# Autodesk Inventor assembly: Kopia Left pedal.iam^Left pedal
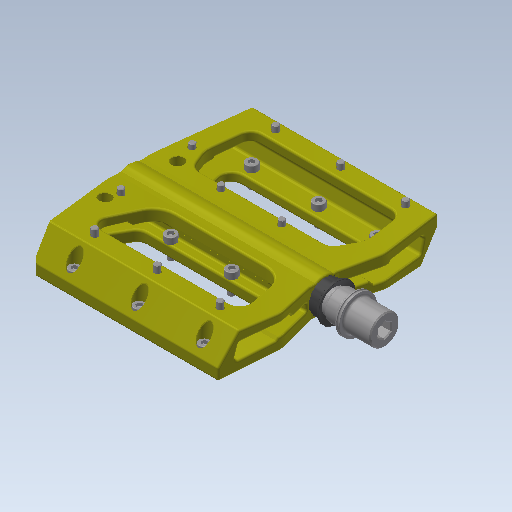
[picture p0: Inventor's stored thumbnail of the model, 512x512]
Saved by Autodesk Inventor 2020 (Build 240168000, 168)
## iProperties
Created: 2017-10
Part Number: Kopia Left pedal.iam^Left pedal
Material: Ogólny
Document SubType Name: Assembly
Designer: Tomasz
Sending System: SolidWorks 2017
Last Author: Tomasz
Last Saved: 2017-11-20
Author: Tomasz
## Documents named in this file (9)
- C:\Users\bruno\Documents\1-Cours-2020-21\1STI2D-2020-21\IT\6. Antivol\Inventor-Antivol\INVENTOR 2018_Steel Hardtail B+\Kopia Left pedal.iam^Left pedal.iam
- C:\Users\bruno\Documents\1-Cours-2020-21\1STI2D-2020-21\IT\6. Antivol\Inventor-Antivol\INVENTOR 2018_Steel Hardtail B+\Kopia full left platform body.ipt^Kopia Left pedal.iam_Left pedal.ipt
- C:\Users\bruno\Documents\1-Cours-2020-21\1STI2D-2020-21\IT\6. Antivol\Inventor-Antivol\INVENTOR 2018_Steel Hardtail B+\Kopia Left pedal axle.ipt^Kopia Left pedal.iam_Left pedal.ipt
- C:\Users\bruno\Documents\1-Cours-2020-21\1STI2D-2020-21\IT\6. Antivol\Inventor-Antivol\INVENTOR 2018_Steel Hardtail B+\Kopia Axle nut.ipt^Kopia Left pedal.iam_Left pedal.ipt
- C:\Users\bruno\Documents\1-Cours-2020-21\1STI2D-2020-21\IT\6. Antivol\Inventor-Antivol\INVENTOR 2018_Steel Hardtail B+\Kopia bushing.ipt^Kopia Left pedal.iam_Left pedal.ipt
- C:\Users\bruno\Documents\1-Cours-2020-21\1STI2D-2020-21\IT\6. Antivol\Inventor-Antivol\INVENTOR 2018_Steel Hardtail B+\Kopia Hex bolt axle cap.ipt^Kopia Left pedal.iam_Left pedal.ipt
- C:\Users\bruno\Documents\1-Cours-2020-21\1STI2D-2020-21\IT\6. Antivol\Inventor-Antivol\INVENTOR 2018_Steel Hardtail B+\Kopia seal.ipt^Kopia Left pedal.iam_Left pedal.ipt
- C:\Users\bruno\Documents\1-Cours-2020-21\1STI2D-2020-21\IT\6. Antivol\Inventor-Antivol\INVENTOR 2018_Steel Hardtail B+\Kopia 686-2RS.iam^Kopia Left pedal.iam_Left pedal.iam
- C:\Users\bruno\Documents\1-Cours-2020-21\1STI2D-2020-21\IT\6. Antivol\Inventor-Antivol\INVENTOR 2018_Steel Hardtail B+\ISO 4762 - M3 x 8DIN EN ISO.ipt
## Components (29 placed, 8 different names)
1. Kopia full left platform body.ipt^Kopia Left pedal.iam_Left pedal:1
2. Kopia Left pedal axle.ipt^Kopia Left pedal.iam_Left pedal:1
3. Kopia Axle nut.ipt^Kopia Left pedal.iam_Left pedal:1
4. Kopia bushing.ipt^Kopia Left pedal.iam_Left pedal:1
5. Kopia Hex bolt axle cap.ipt^Kopia Left pedal.iam_Left pedal:1
6. Kopia Hex bolt axle cap.ipt^Kopia Left pedal.iam_Left pedal:2
7. Kopia seal.ipt^Kopia Left pedal.iam_Left pedal:1
8. Kopia 686-2RS.iam^Kopia Left pedal.iam_Left pedal:1 [sub-assembly]
9. Kopia 686-2RS.iam^Kopia Left pedal.iam_Left pedal:2 [sub-assembly]
10. ISO 4762 - M3 x 8DIN EN ISO:40
11. ISO 4762 - M3 x 8DIN EN ISO:21
12. ISO 4762 - M3 x 8DIN EN ISO:22
13. ISO 4762 - M3 x 8DIN EN ISO:23
14. ISO 4762 - M3 x 8DIN EN ISO:24
15. ISO 4762 - M3 x 8DIN EN ISO:25
16. ISO 4762 - M3 x 8DIN EN ISO:26
17. ISO 4762 - M3 x 8DIN EN ISO:27
18. ISO 4762 - M3 x 8DIN EN ISO:28
19. ISO 4762 - M3 x 8DIN EN ISO:29
20. ISO 4762 - M3 x 8DIN EN ISO:30
21. ISO 4762 - M3 x 8DIN EN ISO:31
22. ISO 4762 - M3 x 8DIN EN ISO:32
23. ISO 4762 - M3 x 8DIN EN ISO:33
24. ISO 4762 - M3 x 8DIN EN ISO:34
25. ISO 4762 - M3 x 8DIN EN ISO:35
26. ISO 4762 - M3 x 8DIN EN ISO:36
27. ISO 4762 - M3 x 8DIN EN ISO:37
28. ISO 4762 - M3 x 8DIN EN ISO:38
29. ISO 4762 - M3 x 8DIN EN ISO:39
